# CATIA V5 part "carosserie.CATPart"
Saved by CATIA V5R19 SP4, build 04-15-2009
Part number: carosserie
Material "Emeraude": density 2770 kg/m3, Young's modulus 6e+10 Pa, Poisson ratio 0.27, thermal expansion 7e-06 1/K
Bounding box of the stored display mesh (mm): x -1432.527 to 680, y -500 to 500, z 1.363 to 251.671
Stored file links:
  G:\EU_thinkMotion\CFAO_2010\MMS_groupe1\MMS_groupe1\A reprendre\OK\rdeneffle\carosserie.CATPart
  G:\EU_thinkMotion\CFAO_2010\MMS_groupe1\MMS_groupe1\A reprendre\OK\rdeneffle\systeme d'ouverture de porte de voiture.CATProduct
  G:\EU_thinkMotion\CFAO_2010\MMS_groupe1\MMS_groupe1\A reprendre\OK\rdeneffle\squelette.CATPart
  C:\Program Files\Dassault Systemes\B19\intel_a\startup\materials\French\Catalog.CATMaterial
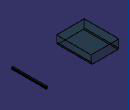
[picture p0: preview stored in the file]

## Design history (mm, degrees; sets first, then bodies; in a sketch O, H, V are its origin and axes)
Set1
  Plane1: linked copy from another document
  Plane2: linked copy from another document
Body1 (main body), material "Emeraude"
  DatumCurve1 to DatumCurve3
  Sketch1 on zx-plane, origin (0, 0, 0), H (-1, 0, 0), V (0, 0, 1)
    line L1 (-680.0001, 92.4604) -> (-630.0001, 92.4604)
    line L2 (-645.0001, 42.4604) -> (-630.0001, 57.4604)
    line L3 (-630.0001, 57.4604) -> (-630.0001, 92.4604)
    line L4 (-665.0001, 42.4604) -> (-680.0001, 57.4604)
    line L5 (-680.0001, 57.4604) -> (-680.0001, 92.4604)
    line L6 (632.5221, 251.352) -> (632.5221, 69.3414)
    line L7 (632.5221, 69.3414) -> (645.384, 54.0256)
    line L8 (645.384, 54.0256) -> (645.384, 17.9396)
    line L9 (659.305, 1.3626) -> (1410.1741, 1.6619)
    point P11 (659.305, 1.3626)
    line L10 (1432.5268, 21.6708) -> (1432.5268, 251.6708)
    point P13 (1432.5268, 21.6708)
    line L11 (1432.5268, 251.6708) -> (632.5221, 251.352)
    line L12 (645.384, 17.9396) -> (659.305, 1.3626)
    point P15 (659.305, 1.3626)
    line L13 (1410.1741, 1.6619) -> (1432.5268, 21.6708)
    point P16 (1432.5268, 21.6708)
    reference intersected line E1 through (0.0077, 51.0999) direction (1, 0.0004) from Plane1
    line L14 (-645.0001, 42.4604) -> (-665.0001, 42.4604)
    point P17 (-645.0001, 42.4604)
    point P18 (-665.0001, 42.4604)
    length L3 = 35
    length L5 = 35
    distance L5 L3 = 50
    angle L4 L5 = 135
    distance L11 L9 = 250
    angle L12 L9 = 50
    angle L9 L7 = 130
    length L7 = 20
    length L8 = 36.086
    length L12 = 21.647
    distance L8 V = 645.384
    length L13 = 30
    distance L3 V = 630.0001
    distance L9 E1 = 50
    horizontal: L1 H, L14 H
    vertical: L3 V, L5 V, L6 V, L8 V, L10 V
    coincidence: L12 P11, P16 L10, L13 P13, P15 P11, P13 P16, P17 L2, P18 L4
  Pad1: profile Sketch1, direction (0, 1, 0), length 500, mirrored extent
